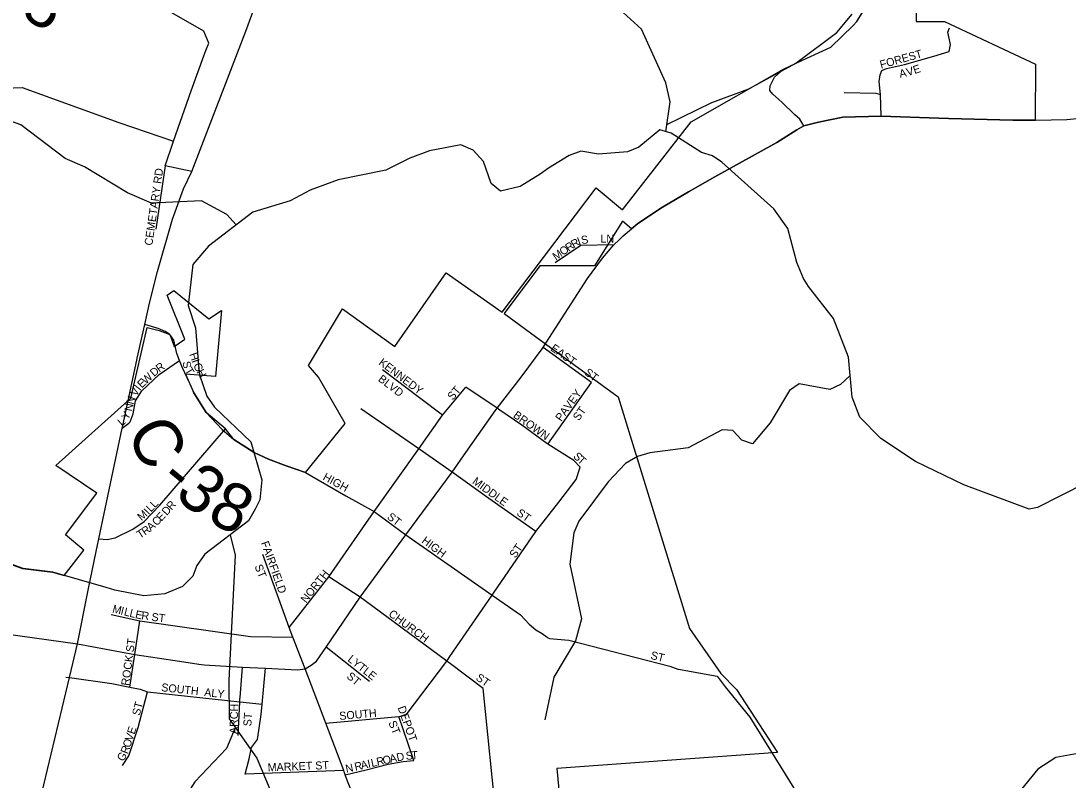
# Model space of a CAD drawing. Extents: x 1525783 to 1900577, y 218250 to 627376.
# Drawn here: x 1668410 to 1674950, y 491035 to 495779 of the extents above; entities that cross this region are included whole.
import ezdxf

# ---------------------------------------------------------------- set-up
doc = ezdxf.new("R2010")
doc.units = 0
for name, color, linetype in [('GM_X_City_Street', 7, 'Continuous'), ('GM_X_City_Street_Text', 7, 'Continuous'), ('GM_X_Corporation', 7, 'Continuous'), ('GM_X_County_Road', 7, 'Continuous'), ('GM_X_County_Road_Text', 7, 'Continuous'), ('GM_X_Minor_River', 7, 'Continuous'), ('GM_X_State_Route', 7, 'Continuous'), ('GM_X_Township_Road', 7, 'Continuous'), ('GM_X_Township_Subdivision', 7, 'Continuous'), ('GM_X_Township_Subdivision_Text', 7, 'Continuous'), ('GM_X_US_Route', 7, 'Continuous')]:
    doc.layers.add(name, color=color, linetype=linetype)

msp = doc.modelspace()

# ---------------------------------------------------------------- linework, layer by layer
at = {"layer": 'GM_X_City_Street'}
for points in [[(1673783, 495182.8), (1673778.3, 495318.8), (1673769.7, 495400), (1673776, 495442.2), (1673786.9, 495469.5), (1673816.6, 495482), (1673928.1, 495507), (1674112.1, 495558.6), (1674207.4, 495586.7), (1674216.8, 495630.5), (1674199.6, 495708.6), (1674209.9, 495736.4)], [(1673300.2, 495123.9), (1673275.3, 495165.8), (1673241.4, 495193.8), (1673162.6, 495271.6), (1673105.7, 495320.5), (1673087.8, 495344.9), (1673089, 495372.4), (1673117.3, 495426.4), (1673172.9, 495477.9)], [(1673551, 495332), (1673750.2, 495326.6), (1673778.3, 495318.8)], [(1672113.7, 494379.7), (1671906.9, 494375.2), (1671747.5, 494266.7)], [(1669464.6, 493513.4), (1669417.8, 493616.1), (1669401.6, 493657.1), (1669384.2, 493701.6), (1669380.3, 493719.2)], [(1671973.9, 493519.8), (1671671.8, 493738.3)], [(1669083.7, 493266.4), (1669093.1, 493274.1), (1669111.3, 493324.2), (1669125.6, 493404.3), (1669166, 493468.3), (1669274.6, 493570.2), (1669401.6, 493657.1)], [(1670899.9, 493424.5), (1670669.2, 493598.1)], [(1671701, 493135.1), (1671973.9, 493519.8)], [(1670085.9, 491988.7), (1670333.8, 492304.3), (1670617.2, 492714), (1670894.8, 493105.6), (1671044, 493316.1), (1671188.3, 493490.1)], [(1671401.7, 493346.8), (1671383.9, 493359.2), (1671188.3, 493490.1)], [(1671044, 493316.1), (1670899.9, 493424.5), (1670899.9, 493424.5)], [(1671332.5, 492795.4), (1671104.7, 492959.9), (1670894.8, 493105.6), (1670533.9, 493356)], [(1671695.4, 493139.1), (1671538.5, 493251.9), (1671401.7, 493346.8)], [(1669043, 493233.2), (1669083.7, 493266.4)], [(1668897.1, 492542.1), (1668949.9, 492538.9), (1668998.2, 492549.1), (1669109.4, 492603.2), (1669181, 492650.1), (1669277.6, 492754), (1669687.2, 493231)], [(1671902.9, 492989.9), (1671863.4, 493032.5), (1671701, 493135.1), (1671695.4, 493139.1)], [(1671361.4, 492202.3), (1671626.7, 492588.9), (1671770.4, 492772.2), (1671877.6, 492914.2), (1671902.9, 492989.9)], [(1670187.4, 492957), (1670438.8, 492811.9), (1670617.2, 492714), (1670815.3, 492568.6)], [(1671626.7, 492588.9), (1671332.5, 492795.4), (1671332.5, 492795.4)], [(1670815.3, 492568.6), (1671353.2, 492190.4), (1671530.3, 492068.5), (1671584, 492009.2), (1671626.6, 491974.8), (1671665.9, 491950.7), (1671696.2, 491929.3), (1671704, 491924.7)], [(1670186.2, 491731.2), (1670107.9, 491927.7), (1670085.9, 491988.7), (1669920.8, 492444)], [(1670559.6, 492155.4), (1670529.3, 492177.8), (1670333.8, 492304.3)], [(1671089.6, 491807), (1671353.2, 492190.4), (1671361.4, 492202.3)], [(1671081.6, 491769.4), (1671069.8, 491778.1), (1670559.6, 492155.4)], [(1668973.3, 492070.9), (1669152.2, 492030.6), (1669845.1, 491931.6), (1670107.9, 491927.7)], [(1669090.3, 491616.8), (1669120.7, 491820.1), (1669152.2, 492030.6)], [(1671704, 491924.7), (1671711.4, 491920.3), (1671833.3, 491909.3), (1672462.9, 491747.5), (1672512.4, 491729.1), (1672516.4, 491728.4)], [(1670587, 491652.3), (1670317.2, 491866.6)], [(1670792.3, 491437.7), (1670816.2, 491442.9), (1671069.8, 491778.1), (1671074.2, 491784.5), (1671089.6, 491807)], [(1671298.3, 491607.5), (1671084.1, 491767.5), (1671081.6, 491769.4)], [(1668691.3, 491679), (1668713.5, 491675.9), (1668977.4, 491639.4), (1668977.8, 491639.3)], [(1669779.2, 491550.6), (1669794.2, 491739.9)], [(1670427.6, 491094.3), (1669811.7, 491072.5), (1669836.1, 491168.7), (1669850.4, 491238.8), (1669888.7, 491288.8), (1669911.3, 491445.2), (1669917.6, 491509.4), (1669937.2, 491734.5)], [(1672516.4, 491728.4), (1672759.1, 491685.6), (1672809.1, 491618.4), (1672962.2, 491429.3), (1673625.8, 490359.2)], [(1668977.8, 491639.3), (1669090.3, 491616.8), (1669155.2, 491603.8), (1669201.7, 491587.3), (1669777.6, 491524.6), (1669917.6, 491509.4)], [(1669044, 491126), (1669084.6, 491187.6), (1669141.7, 491363.5), (1669201.7, 491587.3)], [(1669766.4, 491313.5), (1669777.6, 491524.6), (1669778.5, 491540.5), (1669779.2, 491550.6)], [(1671407.4, 490520.6), (1671403.5, 490558.2), (1671382.3, 490766.9), (1671298.3, 491607.5)], [(1670315, 491390.5), (1670771.4, 491433.1), (1670792.3, 491437.7)], [(1670864.2, 491156.9), (1670771.4, 491433.1)], [(1670436.2, 491067.3), (1670566.2, 491099.3), (1670704.8, 491135), (1670797.6, 491151.4), (1670864.2, 491156.9)]]:
    msp.add_lwpolyline(points, dxfattribs=at)
at = {"layer": 'GM_X_Corporation'}
for points in [[(1673995.3, 496139.6), (1674002.6, 495774.2), (1674178.4, 495774.2), (1674746.6, 495509.3), (1674744, 495158.6), (1674605.7, 495158.6), (1674203.9, 495169.6), (1673783, 495182.8), (1673543.6, 495177.8), (1673391, 495145.9), (1673300.2, 495123.9), (1673257.3, 495099), (1673130.7, 495020.1), (1672745.1, 494804.9), (1672580.2, 494711.2), (1672416.4, 494614.7), (1672263.3, 494513.2), (1672224.1, 494480), (1672166.9, 494528.1), (1671991.7, 494247.7), (1671651, 494247.6), (1671427.5, 493951), (1671686.3, 493761.8), (1672140, 493430.3), (1672585.8, 491983.2), (1672781, 491702.1), (1672880.3, 491601.4), (1673135, 491208.4), (1671758, 491108), (1671854, 490092.1)], [(1668346.1, 492384.3), (1668420, 492357.1), (1668606.5, 492334.2), (1668679.9, 492312.7), (1668803.6, 492471), (1668688.3, 492567.8), (1668884.8, 492828.5), (1668628.6, 493001.3), (1669095.8, 493422), (1669199.5, 493863.1), (1669274.5, 493843.7), (1669340.7, 493819.2), (1669362.4, 493756.9), (1669367.5, 493744), (1669433.9, 493790.5), (1669323.3, 494064.2), (1669365.8, 494094), (1669584.1, 493917.3), (1669662.2, 493969.4), (1669626.1, 493557.5), (1669438.5, 493570.6), (1669491.2, 493455.1), (1669566.8, 493332.2), (1669666.6, 493225.2), (1669740.6, 493162.5), (1669866.7, 493081.4), (1669956.9, 493040.7), (1670067.1, 492997.9), (1670187.4, 492957), (1670435.8, 493262.5), (1670267.9, 493553.4), (1670207, 493626.1), (1670417.9, 493980.6), (1670745.3, 493745.3), (1671067, 494204.8), (1671416.7, 493958), (1672002.6, 494735.6), (1672167, 494597.6), (1672597, 495147.9), (1673172.9, 495477.9), (1673291.8, 495533.3), (1673469.2, 495614.5), (1673608.6, 495750), (1673631.4, 495775.5), (1673711.5, 495904)]]:
    msp.add_lwpolyline(points, dxfattribs=at)
at = {"layer": 'GM_X_County_Road'}
for points in [[(1669566, 495594.3), (1669584.9, 495639.7), (1669553.3, 495714.1), (1669094.7, 495979.9), (1668484.3, 496385.2), (1668268.7, 496617.3), (1667951.4, 496984.5), (1667834.2, 497206), (1667751.4, 497471.4), (1667670.2, 497989.6), (1667613.2, 498190.6), (1667493.7, 498364), (1667213.5, 498548.4), (1667049.3, 498645.8), (1666975.4, 498722.5), (1667064.1, 499093.1), (1667237.3, 499812.4), (1667211.9, 499934.9), (1667032.4, 500150.8), (1665840.2, 501504.5), (1664978.4, 502483.2), (1665027.9, 503878.7)], [(1673172.9, 495477.9), (1673291.8, 495533.4), (1673469.2, 495614.5), (1673608.6, 495750), (1673631.4, 495775.5), (1673667.5, 495832.5), (1673711.5, 495904), (1673758.4, 495994.3), (1673782.2, 496056.4), (1673792.3, 496084.5)], [(1669476.7, 494838), (1669310.6, 494873.7), (1669363.9, 495027.6), (1669472.6, 495341.4), (1669552.3, 495561.6), (1669558.4, 495576.2), (1669566, 495594.3)], [(1669380.3, 493719.2), (1669365.9, 493784.9), (1669340.7, 493819.3), (1669311.5, 493838.3), (1669267.6, 493857.4), (1669185.1, 493881.2)], [(1670187.4, 492957), (1670067.1, 492997.9), (1669956.9, 493040.7), (1669866.7, 493081.4), (1669740.6, 493162.5), (1669687.2, 493231), (1669566.8, 493332.2), (1669491.2, 493455), (1669470.5, 493500.4), (1669464.6, 493513.4)]]:
    msp.add_lwpolyline(points, dxfattribs=at)
at = {"layer": 'GM_X_Minor_River'}
for points in [[(1672438.2, 495086.6), (1672466.2, 495273.3), (1672437.9, 495392.1), (1672286.5, 495727.5), (1672080.6, 495917.2)], [(1672445.1, 495132.4), (1672725.2, 495269.4), (1672957.6, 495354.1), (1673249.3, 495514.1), (1673505.4, 495706.8), (1673601.6, 495821.6)], [(1669755.2, 494503.9), (1669695.3, 494569.5), (1669537.9, 494654.2), (1669226.4, 494640.9), (1669076.7, 494705.4), (1668808.1, 494868), (1668686.4, 494920), (1668410.5, 495128.8), (1668304.6, 495166.6), (1668159.9, 495160.7), (1667868.2, 495008.7), (1667664.5, 494953.6), (1667439.1, 494927)], [(1675056.2, 492888.3), (1674758.6, 492738.4), (1674708.2, 492727.1), (1674298.8, 492879.9), (1673997.8, 493024.9), (1673781.1, 493168.7), (1673650.6, 493303.1), (1673602.3, 493428.2), (1673580.1, 493677.3), (1673485.5, 493919.5), (1673329.9, 494118.5), (1673298.6, 494169.2), (1673256, 494270.1), (1673201, 494481.6), (1673112.6, 494605.4), (1672787.7, 494895.3), (1672730.1, 494936.3), (1672660.1, 494957.4), (1672471.1, 495076.7), (1672401.2, 495097.8), (1672268.9, 494989.5), (1672198.2, 494960.5), (1672017.2, 494947.2), (1671907, 494965), (1671834.2, 494938), (1671706.4, 494857.7), (1671653.6, 494820.4), (1671527.9, 494744.1), (1671404.9, 494715.9), (1671347.4, 494762.9), (1671299.4, 494900), (1671234.2, 494971.3), (1671158.4, 495004.5), (1670962.9, 494967.4), (1670839.7, 494921.1), (1670689.9, 494845.2), (1670391.7, 494785.6)], [(1670391.7, 494785.6), (1670215.9, 494722), (1670092.3, 494653.7), (1669858.2, 494583.1), (1669581.7, 494370.6), (1669483.5, 494255.8), (1669455.4, 494001.4), (1669501.4, 493860.3), (1669519.9, 493627.3), (1669525, 493567), (1669571.1, 493433.9), (1669620.2, 493364.9), (1669845.8, 493148.8), (1669914.4, 492911), (1669902.4, 492786.8), (1669873.4, 492729.1), (1669832.1, 492655.5), (1669559.7, 492447), (1669508.3, 492375.6), (1669483.2, 492309.8), (1669419.9, 492244.5), (1669308.7, 492198.1), (1669178, 492186), (1668997.7, 492222.9), (1668941.7, 492237.8), (1668609.8, 492335.2), (1668423.4, 492358.1), (1668349.5, 492385.3)], [(1673590.3, 493563.3), (1673529.3, 493507.6), (1673462.5, 493476.5), (1673270.2, 493511.6), (1673211.3, 493470.4), (1673089.6, 493267.6), (1672979.1, 493136.9), (1672913.2, 493160), (1672855.9, 493219), (1672789.7, 493224.1), (1672577, 493111), (1672337.5, 493080.5), (1672260.8, 493057.6), (1672185.8, 493012.6), (1672077.5, 492898), (1671894.9, 492654), (1671863.7, 492580.2), (1671838.5, 492384), (1671911.5, 492043.8), (1671873.2, 491906), (1671739.1, 491677.4), (1671682.7, 491411.4)], [(1669718, 492568.2), (1669748.4, 492440.1), (1669708.1, 491660.3), (1669710.3, 491417.5), (1669883.2, 491172.1), (1670055.6, 490760.2), (1670125, 490574.6), (1670125.8, 490498.4), (1669793.3, 490042), (1669764.3, 489986.3), (1669757.2, 489793.8), (1669733.6, 489565.5), (1669652.6, 489396.2), (1669514.2, 489279.9), (1669421.5, 489132.9)], [(1669748.9, 491362.8), (1669693.4, 491233.2), (1669497.2, 491023.6), (1669412.8, 490892.5), (1669257.9, 490748.4), (1669083.3, 490624.7), (1668978.6, 490481.8), (1668943.1, 490396.1), (1668904.9, 490266.3), (1668876.9, 490018)], [(1675033.9, 491205.4), (1674874.7, 491175.8), (1674761.1, 491103.3), (1674640.3, 490954.7), (1674337, 490698.5), (1674239.6, 490509.4), (1674174.6, 490458.3), (1673977.9, 490469.3), (1673853.4, 490469.2), (1673722.3, 490439.1), (1673489.5, 490322.4), (1673330.9, 490200.4), (1672996.1, 489852.5), (1672973, 489792.6), (1672897.4, 489320.3), (1672882.2, 489250.3)]]:
    msp.add_lwpolyline(points, dxfattribs=at)
at = {"layer": 'GM_X_State_Route'}
for points in [[(1672146.9, 494411.8), (1672171, 494435.1), (1672263.3, 494513.2), (1672416.4, 494614.7), (1672580.3, 494711.2), (1672745, 494804.9), (1673130.6, 495020.1), (1673257.3, 495099), (1673300.2, 495123.9), (1673391, 495145.9), (1673473.8, 495161.8), (1673543.6, 495177.8), (1673783, 495182.8), (1674203.9, 495169.6), (1674605.7, 495158.7), (1674746.2, 495158.7), (1674943, 495161.8), (1675004.9, 495168.1)], [(1671689.1, 493765.2), (1671949.9, 494170.2), (1672043.5, 494295.9), (1672113.7, 494379.7), (1672146.9, 494411.8)], [(1671371.7, 493341.8), (1671383.9, 493359.2), (1671533.8, 493553.2), (1671671.8, 493738.3), (1671689.1, 493765.2)], [(1671189.7, 493081.5), (1671371.7, 493341.8)], [(1670186.2, 491731.2), (1670224, 491752.6), (1670256, 491779.2), (1670317.2, 491866.6), (1670529.3, 492177.8), (1670815.3, 492568.6), (1671104.7, 492959.9), (1671189.7, 493081.5)], [(1667185.8, 492067.7), (1667536, 492036.5), (1667658, 492029.4), (1667784.3, 492029.4), (1667931.5, 492018.6), (1668033.5, 492009.7), (1668097.5, 491996.9), (1668151.2, 491986.7), (1668227.7, 491966.8), (1668301.8, 491950.2), (1668763.5, 491886)], [(1668763.5, 491886), (1669120.7, 491820.1), (1669401.5, 491778.2), (1669521.7, 491760.5)], [(1669521.7, 491760.5), (1669554.8, 491755.6), (1669794.2, 491739.9), (1669937.2, 491734.5), (1670138.1, 491724.6), (1670186.2, 491731.2)], [(1670429.7, 491087.6), (1670427.6, 491094.3), (1670315, 491390.5), (1670186.2, 491731.2)], [(1670795.3, 490094.3), (1670724.5, 490285.4), (1670642.7, 490521.9), (1670617.5, 490593.4), (1670591.2, 490670.9), (1670449.3, 491028), (1670436.2, 491067.3), (1670429.7, 491087.6)]]:
    msp.add_lwpolyline(points, dxfattribs=at)
at = {"layer": 'GM_X_Township_Road'}
msp.add_lwpolyline([(1663907.8, 494045.3), (1663969.5, 494023.9), (1664044.1, 494015.7), (1664110.5, 494021.2), (1664218.2, 494040.5), (1664317.7, 494076.5), (1664425.5, 494142.8), (1664516.7, 494223), (1664808.8, 494412.2), (1665578.9, 494814.6), (1665976.2, 495040.8), (1666242.4, 495195.6), (1666417.7, 495276.7), (1666646.9, 495293.3), (1668417.7, 495362.2), (1669021.3, 495143.6), (1669363.9, 495027.6)], dxfattribs=at)
at = {"layer": 'GM_X_Township_Subdivision'}
msp.add_lwpolyline([(1669310.6, 494873.7), (1669253, 494476.8)], dxfattribs=at)
at = {"layer": 'GM_X_US_Route'}
for points in [[(1669185.1, 493881.2), (1669212.3, 494015.8), (1669264, 494212.7), (1669358, 494539.4), (1669425.6, 494729.1), (1669476.7, 494838), (1669814.3, 495715.3), (1670432.4, 497398.6), (1670906.9, 498657.5), (1671182.9, 499389.8), (1671389.8, 499835.6), (1671397.8, 499852.2)], [(1669136.6, 493672.1), (1669185.1, 493881.2)], [(1668880.7, 492464.5), (1668897.1, 492542.1), (1669043, 493233.2), (1669044.5, 493240.2), (1669136, 493669.5), (1669136.6, 493672.1)], [(1668763.5, 491886), (1668829.3, 492221), (1668880.7, 492464.5)], [(1668531.1, 490909.9), (1668713.5, 491675.9), (1668763.5, 491886)]]:
    msp.add_lwpolyline(points, dxfattribs=at)

# ---------------------------------------------------------------- texts
at = {"layer": 'GM_X_City_Street_Text'}
for s, rotation, p in [('FOREST', 15.34889, (1673782.4, 495480.4)), ('A', 12.75874, (1673901.6, 495422.7)), ('V', 16.56864, (1673948.1, 495433.4)), ('E', 18.34549, (1673991.9, 495446.4)), ('I', 20.24313, (1671895.3, 494376)), ('S', 10.55189, (1671913.8, 494383)), ('LN', 0.00001, (1672029.5, 494394)), ('O', 34.77999, (1671795.3, 494310.1)), ('R', 34.77999, (1671831.4, 494335.2)), ('R', 29.93437, (1671863, 494357.2)), ('M', 34.77999, (1671751.9, 494280)), ('H', 288.89807, (1669460.9, 493696.5)), ('EAST', 324.46159, (1671713.8, 493723.4)), ('R', 35.73812, (1669274.7, 493580.9)), ('S', 281.38495, (1669418.8, 493647.2)), ('I', 288.8786, (1669475.1, 493654.9)), ('G', 296.08636, (1669484.8, 493627.7)), ('KENNEDY', 322.95827, (1670640.4, 493635.3)), ('W', 42.51457, (1669190.7, 493505.6)), ('D', 40.65344, (1669242.2, 493552.9)), ('T', 300.48429, (1669432.2, 493595.7)), ('H', 298.86384, (1669505.4, 493585.9)), ('ST', 322.4371, (1671925.2, 493573.6)), ('E', 44.16912, (1669165.7, 493481.4)), ('BLVD', 322.52765, (1670637.1, 493532.5)), ('V', 58.00156, (1669130.9, 493429.1)), ('I', 52.28217, (1669153.5, 493465.4)), ('ST', 50.19084, (1671107.1, 493405)), ('PAVEY', 53.8793, (1671784.3, 493272.5)), ('N', 80.33707, (1669105.5, 493337)), ('N', 71.86227, (1669112.5, 493378.5)), ('Y', 61.61162, (1669078.9, 493281.8)), ('BROWN', 324.45987, (1671480.6, 493305.4)), ('ST', 55.30921, (1671894.5, 493276.2)), ('L', 41.32726, (1669040.7, 493243.8)), ('S', 316.66197, (1671856, 493053.4)), ('T', 317.8484, (1671882.4, 493028.4)), ('HIGH', 331.25881, (1670291.6, 492914.4)), ('MIDDLE', 323.97056, (1671225.4, 492891.8)), ('M', 40.69414, (1669163.6, 492652.4)), ('I', 46.57949, (1669207.7, 492690.6)), ('L', 46.54607, (1669222.8, 492706.6)), ('L', 47.04145, (1669247.3, 492732.5)), ('D', 47.88563, (1669321, 492685.1)), ('R', 48.98517, (1669351.2, 492718.6)), ('ST', 325.29786, (1671502.5, 492693.9)), ('C', 45.96227, (1669259, 492620.2)), ('E', 46.39592, (1669286.8, 492649)), ('ST', 322.42654, (1670693.2, 492671.6)), ('T', 32.14436, (1669152.9, 492542)), ('R', 34.99403, (1669185, 492562.3)), ('A', 40.28502, (1669221.4, 492588.1)), ('FAIRFIELD', 289.70631, (1669908.8, 492517.8)), ('HIGH', 323.13011, (1670908.7, 492522.1)), ('ST', 55.30921, (1671498.2, 492418.8)), ('ST', 291.80393, (1669868.4, 492371.7)), ('NORTH', 51.7089, (1670191.7, 492137.6)), ('M', 346.02118, (1668978.2, 492083.7)), ('I', 346.05489, (1669029.5, 492070.9)), ('L', 346.01014, (1669050.8, 492065.6)), ('L', 346.049, (1669085, 492057.1)), ('E', 347.89397, (1669120.8, 492048.3)), ('R', 353.69339, (1669160.6, 492040)), ('ST', 352.88003, (1669223.5, 492031.1)), ('CHURCH', 323.32406, (1670701.9, 492064.5)), ('ROCK ST', 82.14604, (1669085.4, 491622.6)), ('LYTLE', 321.54618, (1670446.9, 491782.7)), ('ST', 345.96055, (1672339.8, 491793.3)), ('ST', 320.2016, (1670440.5, 491676.9)), ('ST', 325.30922, (1671247.3, 491664.3)), ('SOUTH', 353.80013, (1669284.9, 491591.1)), ('ALY', 354.09695, (1669553.3, 491560.4)), ('ST', 75.06222, (1669151.6, 491434.6)), ('ARCH', 88.52645, (1669762.9, 491322.4)), ('SOUTH', 4.96687, (1670400.7, 491410.8)), ('DEPOT', 289.65318, (1670762.4, 491488.1)), ('ST', 86.41175, (1669848.8, 491370.2)), ('E', 71.97115, (1669119.1, 491318)), ('ST', 291.80393, (1670704.4, 491394.9)), ('O', 71.97748, (1669091.8, 491234.3)), ('V', 71.97972, (1669105.4, 491276.2)), ('R', 69.16325, (1669076.9, 491194.8)), ('G', 57.01919, (1669047.7, 491147.6)), ('MARKET ST', 2.20131, (1669952.3, 491089.6)), ('A', 12.64733, (1670537.9, 491101.8)), ('I', 12.6636, (1670580.8, 491111.4)), ('L', 12.64439, (1670602.3, 491116.2)), ('R', 12.63418, (1670636.6, 491123.9)), ('O', 12.66339, (1670675.3, 491132.6)), ('A', 12.64733, (1670718.2, 491142.2)), ('D', 10.6841, (1670760.7, 491151.8)), ('S', 4.97921, (1670815.7, 491161.4)), ('T', 4.78633, (1670850.8, 491164.4)), ('N', 12.64733, (1670443.4, 491080.6)), ('R', 12.65787, (1670499.3, 491093.1))]:
    msp.add_text(s, height=50, rotation=rotation, dxfattribs=at).set_placement(p)
at = {"layer": 'GM_X_County_Road_Text'}
for s, rotation, p in [('8', 326.93016, (1668395.2, 495821.8)), ('C', 298.17282, (1669062.6, 493205.6)), ('3', 322.06349, (1669361.4, 492806.4)), ('-', 320.57436, (1669259.6, 492890)), ('8', 333.4873, (1669562.4, 492658))]:
    msp.add_text(s, height=300, rotation=rotation, dxfattribs=at).set_placement(p)
at = {"layer": 'GM_X_Township_Subdivision_Text'}
msp.add_text('CEMETARY RD', height=50, rotation=81.86989, dxfattribs=at).set_placement((1669230.6, 494372.7))

doc.saveas('drawing.dxf')
